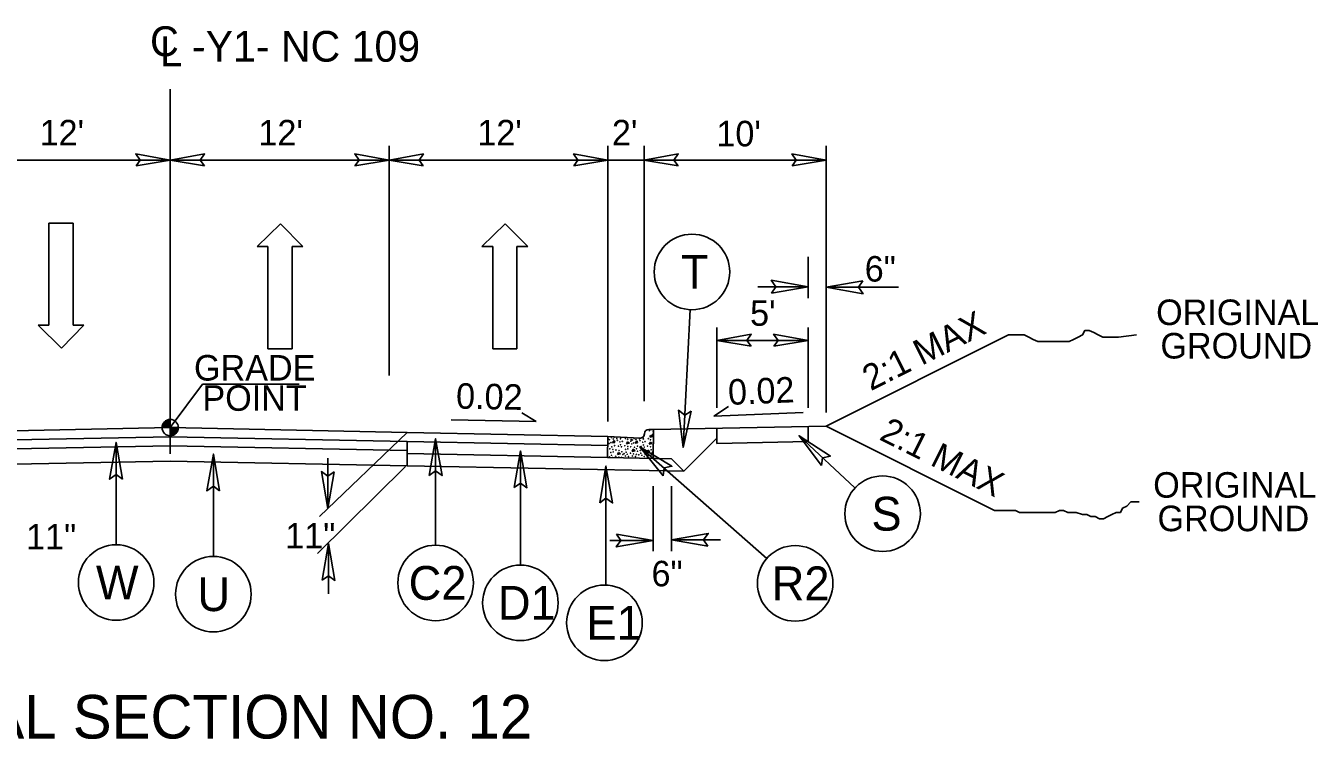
# Model space of a CAD drawing. Extents: x 1640342 to 1730599, y 538663 to 843747.
# Drawn here: x 1730318.6 to 1730389.5, y 539090.2 to 539129.3 of the extents above; entities that cross this region are included whole.
import ezdxf

# ---------------------------------------------------------------- set-up
doc = ezdxf.new("R2010")
doc.units = 0
for name, color, linetype in [('Default', 7, 'Continuous'), ('Typical Curb CELL', 7, 'Continuous'), ('Typical Grade Point Symbol CELL', 7, 'Continuous'), ('Typical Hinge Slope Arterial CELL', 7, 'Continuous'), ('Typical Hinge Slope Interstate CELL', 7, 'Continuous'), ('Typical ID Circle CELL', 7, 'Continuous'), ('Typical Pavement Slope CELL', 7, 'Continuous'), ('Typical Pavement Slope Information CELL', 7, 'Continuous'), ('Typical Shoulder Slope CELL', 7, 'Continuous'), ('Typical Terminator CELL', 7, 'Continuous'), ('Typical Text Centerline CELL', 7, 'Continuous'), ('Typical Text Grade Point CELL', 7, 'Continuous'), ('Typical Text ID Circle CELL', 7, 'Continuous'), ('Typical Text Label CELL', 7, 'Continuous')]:
    doc.layers.add(name, color=color, linetype=linetype)

msp = doc.modelspace()

# ---------------------------------------------------------------- linework, layer by layer
at = {"layer": 'Default'}
for p, q in [((1730350.518, 539107.601), (1730350.518, 539122.704)), ((1730352.514, 539108.706), (1730352.514, 539122.704)), ((1730362.489, 539108.08), (1730362.489, 539122.704)), ((1730314.518, 539121.925), (1730326.518, 539121.925)), ((1730326.518, 539121.926), (1730338.518, 539121.926)), ((1730338.518, 539121.926), (1730350.518, 539121.926)), ((1730350.518, 539121.926), (1730352.51, 539121.926)), ((1730362.489, 539121.926), (1730352.488, 539121.926)), ((1730319.871, 539112.875), (1730319.871, 539118.471)), ((1730319.871, 539118.471), (1730321.19, 539118.471)), ((1730321.19, 539118.471), (1730321.19, 539112.875)), ((1730332.558, 539118.436), (1730331.279, 539117.177)), ((1730333.797, 539117.177), (1730332.558, 539118.436)), ((1730344.881, 539118.436), (1730343.602, 539117.177)), ((1730346.12, 539117.177), (1730344.881, 539118.436)), ((1730331.279, 539117.177), (1730331.879, 539117.177)), ((1730331.879, 539117.177), (1730331.879, 539111.581)), ((1730333.198, 539111.581), (1730333.198, 539117.177)), ((1730333.198, 539117.177), (1730333.797, 539117.177)), ((1730343.602, 539117.177), (1730344.201, 539117.177)), ((1730344.201, 539117.177), (1730344.201, 539111.581)), ((1730345.52, 539111.581), (1730345.52, 539117.177)), ((1730345.52, 539117.177), (1730346.12, 539117.177)), ((1730361.489, 539116.615), (1730361.489, 539114.356)), ((1730358.739, 539114.975), (1730361.489, 539114.975)), ((1730366.458, 539114.951), (1730362.489, 539114.951)), ((1730320.551, 539111.616), (1730319.272, 539112.875)), ((1730319.272, 539112.875), (1730319.871, 539112.875)), ((1730321.79, 539112.875), (1730320.551, 539111.616)), ((1730321.19, 539112.875), (1730321.79, 539112.875)), ((1730356.489, 539108.334), (1730356.489, 539112.737)), ((1730361.489, 539108.334), (1730361.489, 539112.737)), ((1730356.489, 539112.04), (1730361.489, 539112.04)), ((1730331.879, 539111.581), (1730333.198, 539111.581)), ((1730344.201, 539111.581), (1730345.52, 539111.581)), ((1730339.507, 539106.988), (1730334.698, 539102.384)), ((1730339.426, 539105.119), (1730334.59, 539100.352)), ((1730335.166, 539105.582), (1730335.166, 539102.832)), ((1730352.997, 539104.042), (1730352.997, 539100.481)), ((1730353.997, 539104.042), (1730353.997, 539100.481)), ((1730335.189, 539098.146), (1730335.189, 539100.896)), ((1730350.628, 539101.076), (1730352.997, 539101.076)), ((1730356.699, 539101.1), (1730353.997, 539101.1))]:
    msp.add_line(p, q, dxfattribs=at)
for points in [[(1730324.644, 539121.603), (1730326.518, 539121.925), (1730324.633, 539122.259), (1730324.873, 539121.925)], [(1730328.392, 539121.604), (1730326.518, 539121.926), (1730328.402, 539122.26), (1730328.163, 539121.926)], [(1730336.644, 539121.604), (1730338.518, 539121.926), (1730336.633, 539122.26), (1730336.873, 539121.926)], [(1730340.392, 539121.605), (1730338.518, 539121.927), (1730340.402, 539122.261), (1730340.163, 539121.927)], [(1730348.643, 539121.604), (1730350.518, 539121.926), (1730348.633, 539122.26), (1730348.873, 539121.926)], [(1730354.363, 539121.604), (1730352.488, 539121.926), (1730354.373, 539122.26), (1730354.134, 539121.926)], [(1730360.615, 539121.604), (1730362.489, 539121.926), (1730360.605, 539122.26), (1730360.844, 539121.926)], [(1730358.364, 539111.718), (1730356.489, 539112.04), (1730358.374, 539112.374), (1730358.135, 539112.04)], [(1730359.615, 539111.718), (1730361.489, 539112.04), (1730359.605, 539112.374), (1730359.844, 539112.04)]]:
    msp.add_lwpolyline(points, close=True, dxfattribs=at)
at = {"layer": 'Typical Curb CELL'}
for p, q in [((1730353.022, 539107.156), (1730352.761, 539107.16)), ((1730352.997, 539105.563), (1730353.022, 539107.156)), ((1730350.5, 539105.613), (1730350.518, 539106.778)), ((1730350.518, 539106.778), (1730352.265, 539106.679)), ((1730350.773, 539106.431), (1730350.861, 539106.549)), ((1730350.893, 539106.435), (1730350.773, 539106.431)), ((1730350.861, 539106.549), (1730350.893, 539106.435)), ((1730351.537, 539106.368), (1730351.601, 539106.482)), ((1730351.703, 539106.405), (1730351.537, 539106.368)), ((1730351.601, 539106.482), (1730351.703, 539106.405)), ((1730352.021, 539106.412), (1730352.108, 539106.53)), ((1730352.141, 539106.416), (1730352.021, 539106.412)), ((1730352.108, 539106.53), (1730352.141, 539106.416)), ((1730352.518, 539106.914), (1730352.518, 539106.924)), ((1730352.784, 539106.349), (1730352.848, 539106.462)), ((1730352.95, 539106.386), (1730352.784, 539106.349)), ((1730352.826, 539106.826), (1730352.841, 539106.735)), ((1730352.979, 539106.779), (1730352.826, 539106.826)), ((1730352.841, 539106.735), (1730352.979, 539106.779)), ((1730352.848, 539106.462), (1730352.95, 539106.386)), ((1730351.04, 539105.787), (1730351.104, 539105.901)), ((1730351.206, 539105.824), (1730351.04, 539105.787)), ((1730351.104, 539105.901), (1730351.206, 539105.824)), ((1730351.846, 539105.956), (1730351.91, 539106.069)), ((1730352.012, 539105.993), (1730351.846, 539105.956)), ((1730351.91, 539106.069), (1730352.012, 539105.993)), ((1730352.651, 539105.9), (1730352.716, 539106.013)), ((1730352.817, 539105.937), (1730352.651, 539105.9)), ((1730352.716, 539106.013), (1730352.817, 539105.937))]:
    msp.add_line(p, q, dxfattribs=at)
for centre in [(1730352.79, 539107.084), (1730353.006, 539107.046), (1730350.53, 539106.532), (1730350.549, 539106.629), (1730350.585, 539106.388), (1730350.604, 539106.594), (1730350.682, 539106.433), (1730350.715, 539106.717), (1730350.81, 539106.63), (1730350.858, 539106.731), (1730351.005, 539106.666), (1730351.032, 539106.564), (1730351.179, 539106.476), (1730351.21, 539106.647), (1730351.228, 539106.697), (1730351.305, 539106.503), (1730351.484, 539106.665), (1730351.603, 539106.612), (1730351.778, 539106.513), (1730351.797, 539106.609), (1730351.833, 539106.369), (1730351.852, 539106.574), (1730351.93, 539106.413), (1730351.962, 539106.666), (1730352.058, 539106.611), (1730352.253, 539106.647), (1730352.28, 539106.545), (1730352.427, 539106.457), (1730352.458, 539106.628), (1730352.476, 539106.678), (1730352.553, 539106.484), (1730352.732, 539106.646), (1730352.851, 539106.593), (1730352.952, 539106.865), (1730350.52, 539106.224), (1730350.599, 539105.657), (1730350.62, 539106.097), (1730350.682, 539105.896), (1730350.714, 539105.741), (1730350.73, 539106.198), (1730350.77, 539105.626), (1730350.79, 539106.066), (1730350.808, 539105.922), (1730350.89, 539106.264), (1730350.947, 539105.686), (1730350.957, 539106.031), (1730351.095, 539106.238), (1730351.118, 539105.644), (1730351.128, 539106), (1730351.211, 539106.322), (1730351.266, 539106.207), (1730351.271, 539105.624), (1730351.282, 539105.932), (1730351.337, 539105.788), (1730351.404, 539105.826), (1730351.444, 539106.267), (1730351.472, 539105.704), (1730351.488, 539106.064), (1730351.52, 539105.91), (1730351.575, 539105.795), (1730351.614, 539106.224), (1730351.614, 539106.091), (1730351.643, 539105.672), (1730351.753, 539105.855), (1730351.768, 539106.205), (1730351.856, 539105.704), (1730351.923, 539105.812), (1730351.978, 539106.179), (1730352.027, 539105.672), (1730352.077, 539105.793), (1730352.088, 539106.101), (1730352.138, 539106.245), (1730352.142, 539105.957), (1730352.21, 539105.77), (1730352.294, 539106.008), (1730352.325, 539105.853), (1730352.343, 539106.219), (1730352.381, 539105.739), (1730352.42, 539106.034), (1730352.459, 539106.303), (1730352.512, 539105.675), (1730352.514, 539106.188), (1730352.559, 539105.799), (1730352.683, 539105.644), (1730352.692, 539106.248), (1730352.729, 539105.756), (1730352.862, 539106.205), (1730352.883, 539105.736), (1730352.893, 539106.044), (1730352.948, 539105.901)]:
    msp.add_circle(centre, 0.00801, dxfattribs=at)
for centre, start, end in [((1730352.758, 539106.921), 89.1186, 179.1186), ((1730352.279, 539106.917), 266.73414, 359.1186)]:
    msp.add_arc(centre, 0.239, start, end, dxfattribs=at)
at = {"layer": 'Typical Grade Point Symbol CELL'}
for p, q in [((1730326.071, 539107.258), (1730326.518, 539107.258)), ((1730326.518, 539107.258), (1730326.518, 539107.705)), ((1730326.519, 539106.811), (1730326.518, 539107.258)), ((1730326.965, 539107.258), (1730326.518, 539107.258)), ((1730326.518, 539107.258), (1730326.519, 539106.811))]:
    msp.add_line(p, q, dxfattribs=at)
for points in [[(1730326.076, 539107.322), (1730326.076, 539107.258)], [(1730326.085, 539107.368), (1730326.085, 539107.258)], [(1730326.094, 539107.398), (1730326.094, 539107.258)], [(1730326.103, 539107.423), (1730326.103, 539107.258)], [(1730326.112, 539107.444), (1730326.112, 539107.258)], [(1730326.121, 539107.463), (1730326.121, 539107.258)], [(1730326.129, 539107.479), (1730326.129, 539107.258)], [(1730326.138, 539107.494), (1730326.138, 539107.258)], [(1730326.147, 539107.508), (1730326.147, 539107.258)], [(1730326.156, 539107.521), (1730326.156, 539107.258)], [(1730326.165, 539107.533), (1730326.165, 539107.258)], [(1730326.174, 539107.543), (1730326.174, 539107.258)], [(1730326.183, 539107.554), (1730326.183, 539107.258)], [(1730326.192, 539107.564), (1730326.192, 539107.258)], [(1730326.201, 539107.573), (1730326.201, 539107.258)], [(1730326.21, 539107.582), (1730326.21, 539107.258)], [(1730326.219, 539107.59), (1730326.219, 539107.258)], [(1730326.228, 539107.598), (1730326.228, 539107.258)], [(1730326.237, 539107.606), (1730326.237, 539107.258)], [(1730326.246, 539107.613), (1730326.246, 539107.258)], [(1730326.255, 539107.619), (1730326.255, 539107.258)], [(1730326.264, 539107.626), (1730326.264, 539107.258)], [(1730326.273, 539107.632), (1730326.273, 539107.258)], [(1730326.282, 539107.638), (1730326.282, 539107.258)], [(1730326.29, 539107.643), (1730326.29, 539107.258)], [(1730326.299, 539107.648), (1730326.299, 539107.258)], [(1730326.308, 539107.653), (1730326.308, 539107.258)], [(1730326.317, 539107.658), (1730326.317, 539107.258)], [(1730326.326, 539107.662), (1730326.326, 539107.258)], [(1730326.335, 539107.666), (1730326.335, 539107.258)], [(1730326.344, 539107.67), (1730326.344, 539107.258)], [(1730326.353, 539107.674), (1730326.353, 539107.258)], [(1730326.362, 539107.678), (1730326.362, 539107.258)], [(1730326.371, 539107.681), (1730326.371, 539107.258)], [(1730326.38, 539107.684), (1730326.38, 539107.258)], [(1730326.389, 539107.687), (1730326.389, 539107.258)], [(1730326.398, 539107.689), (1730326.398, 539107.258)], [(1730326.407, 539107.692), (1730326.407, 539107.258)], [(1730326.416, 539107.694), (1730326.416, 539107.258)], [(1730326.425, 539107.695), (1730326.425, 539107.258)], [(1730326.434, 539107.698), (1730326.434, 539107.258)], [(1730326.443, 539107.7), (1730326.443, 539107.258)], [(1730326.451, 539107.7), (1730326.451, 539107.258)], [(1730326.46, 539107.701), (1730326.46, 539107.258)], [(1730326.469, 539107.702), (1730326.469, 539107.258)], [(1730326.478, 539107.703), (1730326.478, 539107.258)], [(1730326.487, 539107.704), (1730326.487, 539107.258)], [(1730326.496, 539107.704), (1730326.496, 539107.258)], [(1730326.505, 539107.705), (1730326.505, 539107.258)], [(1730326.514, 539107.705), (1730326.514, 539107.705), (1730326.514, 539107.258)], [(1730326.525, 539107.258), (1730326.525, 539106.811), (1730326.525, 539106.811)], [(1730326.534, 539107.258), (1730326.534, 539106.811)], [(1730326.543, 539107.258), (1730326.543, 539106.812)], [(1730326.552, 539107.258), (1730326.552, 539106.812)], [(1730326.561, 539107.258), (1730326.561, 539106.813)], [(1730326.57, 539107.258), (1730326.57, 539106.814)], [(1730326.579, 539107.258), (1730326.579, 539106.815)], [(1730326.588, 539107.258), (1730326.588, 539106.817)], [(1730326.597, 539107.258), (1730326.597, 539106.818)], [(1730326.606, 539107.258), (1730326.606, 539106.82)], [(1730326.614, 539107.258), (1730326.614, 539106.822)], [(1730326.623, 539107.258), (1730326.623, 539106.824)], [(1730326.632, 539107.258), (1730326.632, 539106.826)], [(1730326.641, 539107.258), (1730326.641, 539106.829)], [(1730326.65, 539107.258), (1730326.65, 539106.831)], [(1730326.659, 539107.258), (1730326.659, 539106.834)], [(1730326.668, 539107.258), (1730326.668, 539106.837)], [(1730326.677, 539107.258), (1730326.677, 539106.84)], [(1730326.686, 539107.258), (1730326.686, 539106.844)], [(1730326.695, 539107.258), (1730326.695, 539106.848)], [(1730326.704, 539107.258), (1730326.704, 539106.852)], [(1730326.713, 539107.258), (1730326.713, 539106.856)], [(1730326.722, 539107.258), (1730326.722, 539106.86)], [(1730326.731, 539107.258), (1730326.731, 539106.865)], [(1730326.74, 539107.258), (1730326.74, 539106.87)], [(1730326.749, 539107.258), (1730326.749, 539106.875)], [(1730326.758, 539107.258), (1730326.758, 539106.881)], [(1730326.767, 539107.258), (1730326.767, 539106.886)], [(1730326.776, 539107.258), (1730326.776, 539106.892)], [(1730326.784, 539107.258), (1730326.784, 539106.898)], [(1730326.793, 539107.258), (1730326.793, 539106.905)], [(1730326.802, 539107.258), (1730326.802, 539106.912)], [(1730326.811, 539107.258), (1730326.811, 539106.92)], [(1730326.82, 539107.258), (1730326.82, 539106.928)], [(1730326.829, 539107.258), (1730326.829, 539106.936)], [(1730326.838, 539107.258), (1730326.838, 539106.945)], [(1730326.847, 539107.258), (1730326.847, 539106.955)], [(1730326.856, 539107.258), (1730326.856, 539106.965)], [(1730326.865, 539107.258), (1730326.865, 539106.976)], [(1730326.874, 539107.258), (1730326.874, 539106.987)], [(1730326.883, 539107.258), (1730326.883, 539106.999)], [(1730326.892, 539107.258), (1730326.892, 539107.012)], [(1730326.901, 539107.258), (1730326.901, 539107.026)], [(1730326.91, 539107.258), (1730326.91, 539107.042)], [(1730326.919, 539107.258), (1730326.919, 539107.058)], [(1730326.928, 539107.258), (1730326.928, 539107.077)], [(1730326.937, 539107.258), (1730326.937, 539107.098)], [(1730326.945, 539107.258), (1730326.945, 539107.125)], [(1730326.954, 539107.258), (1730326.954, 539107.157)], [(1730326.963, 539107.258), (1730326.963, 539107.209)]]:
    msp.add_lwpolyline(points, dxfattribs=at)
msp.add_circle((1730326.519, 539107.258), 0.447, dxfattribs=at)
for start, end in [(90.00929, 180.00929), (270.00929, 0.00929)]:
    msp.add_arc((1730326.519, 539107.258), 0.447, start, end, dxfattribs=at)
at = {"layer": 'Typical Hinge Slope Arterial CELL'}
for p, q in [((1730372.482, 539112.342), (1730362.489, 539107.345)), ((1730362.489, 539107.345), (1730371.706, 539102.722))]:
    msp.add_line(p, q, dxfattribs=at)
msp.add_lwpolyline([(1730379.499, 539112.342), (1730378.515, 539112.219), (1730378.269, 539112.219), (1730377.899, 539112.219), (1730377.653, 539112.219), (1730377.406, 539112.342), (1730377.16, 539112.465), (1730376.914, 539112.589), (1730376.668, 539112.589), (1730376.544, 539112.342), (1730376.298, 539112.219), (1730376.052, 539112.096), (1730375.806, 539111.973), (1730375.56, 539111.973), (1730375.313, 539111.973), (1730375.067, 539111.973), (1730374.821, 539111.973), (1730374.575, 539111.973), (1730374.329, 539111.973), (1730374.082, 539111.973), (1730373.836, 539112.096), (1730373.59, 539112.219), (1730373.344, 539112.342), (1730372.974, 539112.342), (1730372.728, 539112.342), (1730372.482, 539112.342)], dxfattribs=at)
at = {"layer": 'Typical Hinge Slope Interstate CELL'}
msp.add_lwpolyline([(1730379.654, 539103.183), (1730379.424, 539103.183), (1730379.194, 539103.183), (1730378.963, 539102.953), (1730378.733, 539102.837), (1730378.617, 539102.607), (1730378.387, 539102.607), (1730378.157, 539102.492), (1730377.926, 539102.376), (1730377.696, 539102.261), (1730377.466, 539102.261), (1730377.235, 539102.376), (1730377.005, 539102.376), (1730376.775, 539102.492), (1730376.544, 539102.492), (1730376.198, 539102.607), (1730375.968, 539102.607), (1730375.738, 539102.607), (1730375.507, 539102.722), (1730375.277, 539102.722), (1730375.047, 539102.607), (1730374.816, 539102.607), (1730374.586, 539102.607), (1730374.356, 539102.607), (1730374.125, 539102.607), (1730373.779, 539102.607), (1730373.434, 539102.607), (1730373.088, 539102.607), (1730372.858, 539102.722), (1730372.513, 539102.722), (1730372.167, 539102.722), (1730371.706, 539102.722)], dxfattribs=at)
at = {"layer": 'Typical ID Circle CELL'}
for p, q in [((1730355.024, 539113.724), (1730354.642, 539106.172)), ((1730323.555, 539100.837), (1730323.555, 539106.446)), ((1730341.069, 539100.814), (1730341.069, 539106.646)), ((1730364.064, 539103.951), (1730361, 539106.812)), ((1730328.885, 539100.197), (1730328.885, 539105.806)), ((1730345.719, 539099.721), (1730345.719, 539105.977)), ((1730359.23, 539100.088), (1730352.274, 539106.208)), ((1730350.413, 539098.627), (1730350.413, 539105.145))]:
    msp.add_line(p, q, dxfattribs=at)
for centre in [(1730355.128, 539115.792), (1730365.578, 539102.537), (1730323.554, 539098.766), (1730341.07, 539098.743), (1730360.785, 539098.72), (1730328.884, 539098.126), (1730345.72, 539097.65), (1730350.327, 539096.558)]:
    msp.add_circle(centre, 2.071, dxfattribs=at)
at = {"layer": 'Typical Pavement Slope CELL'}
for p, q in [((1730338.518, 539110.117), (1730338.518, 539122.704)), ((1730313.518, 539106.998), (1730326.518, 539107.258)), ((1730339.518, 539106.998), (1730326.518, 539107.258)), ((1730313.528, 539106.498), (1730326.528, 539106.758)), ((1730339.508, 539106.498), (1730326.508, 539106.758)), ((1730350.508, 539106.278), (1730339.508, 539106.498)), ((1730350.518, 539106.778), (1730339.518, 539106.998)), ((1730339.518, 539105.998), (1730339.518, 539106.498)), ((1730356.489, 539106.673), (1730354.678, 539104.861)), ((1730313.518, 539105.998), (1730326.518, 539106.258)), ((1730339.518, 539105.998), (1730326.518, 539106.258)), ((1730350.494, 539105.612), (1730339.518, 539105.831)), ((1730313.518, 539105.165), (1730326.518, 539105.425)), ((1730339.518, 539105.164), (1730326.518, 539105.424)), ((1730354.678, 539104.861), (1730339.518, 539105.164)), ((1730353.997, 539105.543), (1730350.5, 539105.613)), ((1730353.997, 539105.543), (1730354.678, 539104.861))]:
    msp.add_line(p, q, dxfattribs=at)
msp.add_lwpolyline([(1730339.518, 539105.998), (1730339.518, 539105.164)], dxfattribs=at)
at = {"layer": 'Typical Pavement Slope Information CELL'}
for p, q in [((1730346.584, 539107.589), (1730345.802, 539108.062)), ((1730356.325, 539107.893), (1730357.138, 539108.408)), ((1730356.325, 539107.893), (1730361.224, 539108.09)), ((1730346.584, 539107.589), (1730341.925, 539107.682))]:
    msp.add_line(p, q, dxfattribs=at)
at = {"layer": 'Typical Shoulder Slope CELL'}
for p, q in [((1730362.489, 539107.345), (1730353.022, 539107.156)), ((1730356.489, 539107.227), (1730356.489, 539106.392)), ((1730361.489, 539106.492), (1730361.489, 539107.327)), ((1730361.489, 539106.492), (1730356.489, 539106.392))]:
    msp.add_line(p, q, dxfattribs=at)
at = {"layer": 'Typical Terminator CELL'}
for points in [[(1730359.482, 539114.629), (1730361.489, 539114.975), (1730359.47, 539115.332), (1730359.727, 539114.975)], [(1730364.497, 539115.297), (1730362.489, 539114.951), (1730364.508, 539114.594), (1730364.252, 539114.951)], [(1730355.088, 539108.16), (1730354.642, 539106.172), (1730354.387, 539108.207), (1730354.731, 539107.932)], [(1730323.901, 539104.438), (1730323.555, 539106.446), (1730323.198, 539104.427), (1730323.555, 539104.684)], [(1730340.723, 539104.638), (1730341.069, 539106.646), (1730341.426, 539104.627), (1730341.069, 539104.883)], [(1730362.231, 539105.189), (1730361, 539106.812), (1730362.719, 539105.695), (1730362.288, 539105.609)], [(1730329.23, 539103.799), (1730328.885, 539105.806), (1730328.528, 539103.787), (1730328.885, 539104.044)], [(1730345.373, 539103.969), (1730345.719, 539105.977), (1730346.076, 539103.958), (1730345.719, 539104.214)], [(1730353.553, 539104.622), (1730352.274, 539106.208), (1730354.026, 539105.142), (1730353.597, 539105.044)], [(1730350.067, 539103.137), (1730350.413, 539105.145), (1730350.77, 539103.126), (1730350.413, 539103.383)], [(1730335.511, 539104.84), (1730335.166, 539102.832), (1730334.809, 539104.851), (1730335.166, 539104.594)], [(1730350.989, 539101.422), (1730352.997, 539101.076), (1730350.978, 539100.719), (1730351.235, 539101.076)], [(1730356.005, 539100.754), (1730353.997, 539101.1), (1730356.016, 539101.457), (1730355.759, 539101.1)], [(1730334.844, 539098.888), (1730335.189, 539100.896), (1730335.546, 539098.877), (1730335.189, 539099.134)]]:
    msp.add_lwpolyline(points, close=True, dxfattribs=at)
at = {"layer": 'Typical Text Centerline CELL'}
msp.add_line((1730326.518, 539105.812), (1730326.518, 539125.812), dxfattribs=at)
at = {"layer": 'Typical Text Grade Point CELL'}
for q in [(1730326.518, 539107.258), (1730333.583, 539109.643)]:
    msp.add_line((1730328.28, 539109.643), q, dxfattribs=at)

# ---------------------------------------------------------------- texts
at = {"layer": 'Default'}
for s, p in [("10'", (1730356.466, 539122.676)), ("5'", (1730358.313, 539112.84)), ('ORIGINAL', (1730380.577, 539112.88)), ('GROUND', (1730380.812, 539111.045)), ('ORIGINAL', (1730380.416, 539103.415)), ('GROUND', (1730380.651, 539101.579)), ('11"', (1730318.618, 539100.577)), ('11"', (1730332.825, 539100.631)), ('6"', (1730352.909, 539098.555))]:
    msp.add_text(s, height=1.4, dxfattribs=at).set_placement(p)
msp.add_text('6"', height=1.4, rotation=360, dxfattribs=at).set_placement((1730364.599, 539115.263))
at = {"layer": 'Typical Hinge Slope Interstate CELL'}
for rotation, p in [(26.56458, (1730364.927, 539109.251)), (333.43542, (1730365.336, 539106.626))]:
    msp.add_text('2:1 MAX', height=1.4, rotation=rotation, dxfattribs=at).set_placement(p)
at = {"layer": 'Typical Pavement Slope Information CELL'}
for s, p in [("12'", (1730319.356, 539122.725)), ("12'", (1730331.356, 539122.726)), ("12'", (1730343.356, 539122.726)), ("2'", (1730350.738, 539122.726))]:
    msp.add_text(s, height=1.4, dxfattribs=at).set_placement(p)
for rotation, p in [(2.30028, (1730357.131, 539108.5)), (358.85426, (1730342.181, 539108.299))]:
    msp.add_text('0.02', height=1.4, rotation=rotation, dxfattribs=at).set_placement(p)
at = {"layer": 'Typical Text Centerline CELL'}
for s, height, rotation, p in [('C', 1.639, 0.04425, (1730325.413, 539127.618)), ('-Y1- NC 109', 1.68295, 359.94168, (1730327.712, 539127.326)), ('L', 1.64, 359.99115, (1730325.958, 539127.059))]:
    msp.add_text(s, height=height, rotation=rotation, dxfattribs=at).set_placement(p)
at = {"layer": 'Typical Text Grade Point CELL'}
for s, p in [('GRADE', (1730327.822, 539109.837)), ('POINT', (1730328.284, 539108.178))]:
    msp.add_text(s, height=1.4, rotation=359.99977, dxfattribs=at).set_placement(p)
at = {"layer": 'Typical Text ID Circle CELL'}
for s, height, p in [('T', 1.854, (1730354.519, 539114.866)), ('S', 1.854, (1730364.967, 539101.61)), ('W', 1.854, (1730322.445, 539097.839)), ('C2', 1.8535, (1730339.593, 539097.817)), ('R2', 1.8535, (1730359.499, 539097.793)), ('U', 1.854, (1730328.01, 539097.199)), ('D1', 1.8535, (1730344.485, 539096.724)), ('E1', 1.8535, (1730349.34, 539095.631))]:
    msp.add_text(s, height=height, dxfattribs=at).set_placement(p)
at = {"layer": 'Typical Text Label CELL'}
msp.add_text('TYPICAL SECTION NO. 12', height=2.38712, rotation=360, dxfattribs=at).set_placement((1730306.986, 539090.213))

doc.saveas('drawing.dxf')
